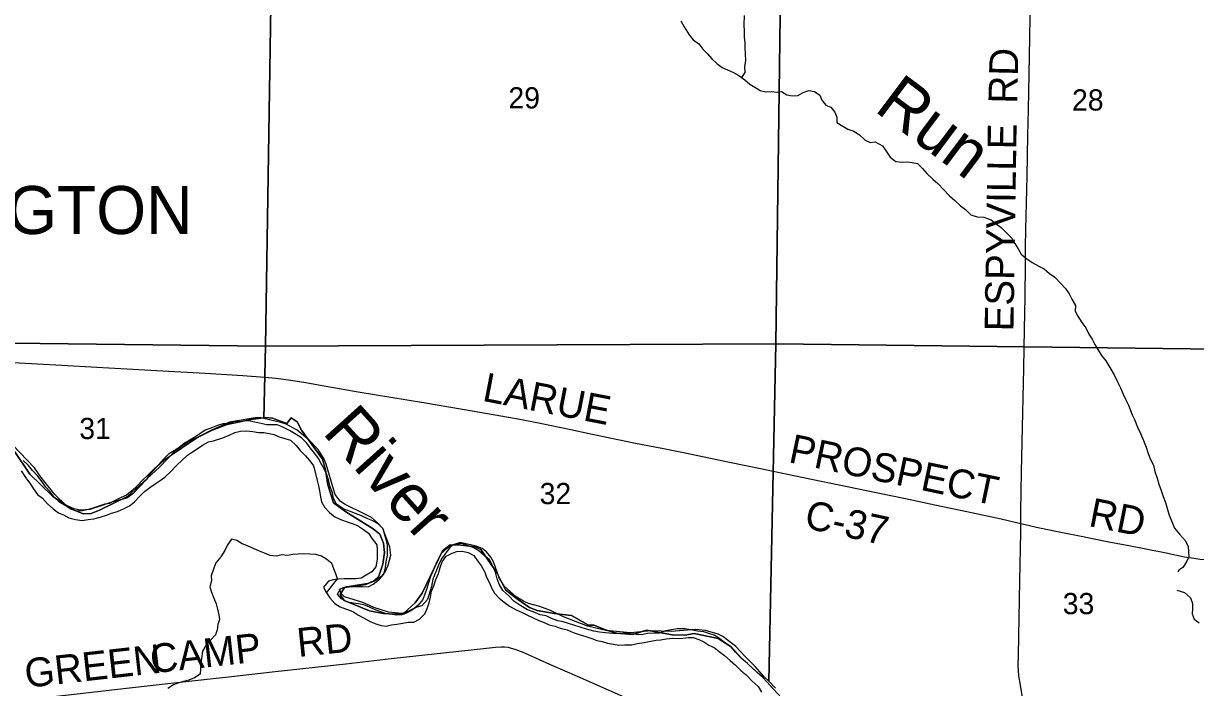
# Model space of a CAD drawing. Extents: x 1584893 to 1934202, y 663575 to 1091909.
# Drawn here: x 1748072 to 1760284, y 934048 to 940964 of the extents above; entities that cross this region are included whole.
import ezdxf

# ---------------------------------------------------------------- set-up
doc = ezdxf.new("R2010")
doc.units = 0
for name, color, linetype in [('GM_X_Corporation_Text', 7, 'Continuous'), ('GM_X_County_Road', 7, 'Continuous'), ('GM_X_County_Road_Text', 7, 'Continuous'), ('GM_X_Major_River', 7, 'Continuous'), ('GM_X_Major_River_Text', 7, 'Continuous'), ('GM_X_Minor_River', 7, 'Continuous'), ('GM_X_Minor_River_Text', 7, 'Continuous'), ('GM_X_Section', 7, 'Continuous'), ('GM_X_Section_Text', 7, 'Continuous'), ('GM_X_Township', 7, 'Continuous'), ('GM_X_Township_Road', 7, 'Continuous'), ('GM_X_Township_Road_Text', 7, 'Continuous')]:
    doc.layers.add(name, color=color, linetype=linetype)

msp = doc.modelspace()

# ---------------------------------------------------------------- linework, layer by layer
at = {"layer": 'GM_X_County_Road'}
for points in [[(1747704, 937447), (1748409, 937408), (1748900, 937380), (1749523, 937347), (1749965, 937321), (1750358, 937297), (1750588, 937281), (1750702, 937270), (1750832, 937253), (1750995, 937228), (1751205, 937192), (1751561, 937129), (1752240, 937015), (1752645, 936949), (1752985, 936890), (1753243, 936844), (1753437, 936806), (1753774, 936736), (1753967, 936695), (1754433, 936598), (1754739, 936537), (1754948, 936495), (1755446, 936392), (1755735, 936333), (1756266, 936223), (1756555, 936163), (1756973, 936076), (1757262, 936017), (1757567, 935952), (1757968, 935866), (1758257, 935804), (1758417, 935767), (1758465, 935757)], [(1758465, 935757), (1758657, 935713), (1758914, 935659), (1759091, 935624), (1759381, 935566), (1759590, 935526), (1759977, 935450), (1760170, 935411), (1760267, 935394), (1760331, 935386), (1760397, 935381), (1760495, 935378), (1760774, 935374), (1760938, 935372), (1761020, 935368), (1761062, 935363)], [(1747714, 933881), (1747761, 933886), (1748511, 933970), (1749147, 934042), (1749701, 934105), (1750239, 934164), (1750663, 934213), (1751430, 934296), (1751903, 934349), (1752896, 934460), (1752991, 934469), (1753049, 934473), (1753084, 934472), (1753123, 934468), (1753154, 934460), (1753192, 934449), (1753269, 934419), (1753584, 934278), (1753840, 934168), (1754320, 933956), (1754513, 933871)]]:
    msp.add_lwpolyline(points, dxfattribs=at)
at = {"layer": 'GM_X_Major_River'}
for points in [[(1751025, 936594), (1750970, 936649), (1750915, 936684), (1750845, 936725), (1750768, 936762), (1750716, 936785), (1750656, 936784), (1750604, 936785), (1750550, 936798), (1750498, 936807), (1750438, 936822), (1750380, 936825), (1750326, 936814), (1750268, 936819), (1750202, 936796), (1750150, 936793), (1750093, 936777), (1750025, 936749), (1749964, 936727), (1749910, 936692), (1749857, 936657), (1749806, 936624), (1749748, 936591), (1749693, 936547), (1749642, 936512), (1749584, 936477), (1749527, 936424), (1749482, 936370), (1749423, 936315), (1749364, 936256), (1749313, 936209), (1749258, 936148), (1749201, 936098), (1749146, 936051), (1749090, 936026), (1749021, 935991), (1748969, 935966), (1748919, 935959), (1748868, 935939), (1748804, 935920), (1748749, 935901), (1748689, 935890), (1748631, 935885), (1748567, 935906), (1748506, 935943), (1748450, 935974), (1748393, 936032), (1748352, 936086), (1748303, 936139), (1748268, 936190), (1748222, 936249), (1748165, 936308), (1748126, 936361), (1748069, 936412)], [(1748049, 936304), (1748094, 936237), (1748137, 936176), (1748178, 936119), (1748219, 936058), (1748271, 936019), (1748322, 935960), (1748381, 935911), (1748436, 935868), (1748488, 935847), (1748544, 935816), (1748614, 935797), (1748685, 935788), (1748748, 935797), (1748806, 935804), (1748870, 935823), (1748939, 935844), (1748989, 935865), (1749053, 935882), (1749114, 935911), (1749177, 935940), (1749229, 935982), (1749280, 936039), (1749335, 936090), (1749390, 936131), (1749443, 936171), (1749495, 936206), (1749546, 936239), (1749607, 936298), (1749666, 936361), (1749725, 936417), (1749782, 936468), (1749832, 936503), (1749883, 936534), (1749936, 936574), (1750000, 936607), (1750051, 936618), (1750151, 936648), (1750214, 936677), (1750276, 936704), (1750335, 936717), (1750395, 936722), (1750461, 936713), (1750521, 936706), (1750575, 936705), (1750631, 936694), (1750684, 936682), (1750738, 936659), (1750794, 936642), (1750854, 936623), (1750913, 936568), (1750956, 936517), (1751011, 936462), (1751056, 936409), (1751094, 936356), (1751107, 936304), (1751133, 936203), (1751146, 936149), (1751155, 936098), (1751166, 936034), (1751178, 935984), (1751209, 935927), (1751260, 935872), (1751315, 935825), (1751387, 935794), (1751444, 935775), (1751496, 935758), (1751554, 935735), (1751615, 935694), (1751667, 935655), (1751706, 935596), (1751753, 935535), (1751758, 935483), (1751759, 935431), (1751758, 935381), (1751745, 935307), (1751702, 935253), (1751644, 935218), (1751589, 935189), (1751535, 935180), (1751413, 935182), (1751355, 935177), (1751300, 935170), (1751250, 935156), (1751199, 935093), (1751228, 935034)], [(1754697, 934616), (1754647, 934615), (1754573, 934610), (1754513, 934597), (1754459, 934600), (1754395, 934609), (1754333, 934614), (1754275, 934609), (1754213, 934610), (1754135, 934617), (1754075, 934626), (1754015, 934636), (1753939, 934655), (1753871, 934678), (1753808, 934699), (1753752, 934714), (1753694, 934733), (1753640, 934744), (1753573, 934769), (1753519, 934794), (1753457, 934805), (1753381, 934836), (1753324, 934857), (1753254, 934899), (1753181, 934948), (1753128, 935003), (1753067, 935058), (1753030, 935125), (1753009, 935179), (1752990, 935250), (1752963, 935311), (1752926, 935379), (1752872, 935424), (1752817, 935473), (1752764, 935502), (1752700, 935527), (1752640, 935550), (1752590, 935543), (1752534, 935528), (1752483, 935495), (1752424, 935444), (1752393, 935386), (1752368, 935332), (1752345, 935275), (1752312, 935205), (1752293, 935139), (1752276, 935081), (1752253, 935020), (1752234, 934964), (1752183, 934906), (1752124, 934859), (1752064, 934822), (1752013, 934807), (1751955, 934802), (1751899, 934811), (1751843, 934818), (1751784, 934839), (1751728, 934860), (1751676, 934887), (1751619, 934910), (1751563, 934921), (1751509, 934926), (1751451, 934938), (1751385, 934972), (1751344, 935022), (1751375, 935076), (1751440, 935101), (1751492, 935098), (1751552, 935101), (1751606, 935100), (1751664, 935097), (1751714, 935125), (1751783, 935176), (1751826, 935229), (1751845, 935297), (1751852, 935357), (1751865, 935423), (1751866, 935481), (1751865, 935537), (1751848, 935600), (1751835, 935650), (1751820, 935700), (1751767, 935753), (1751711, 935786), (1751659, 935805), (1751594, 935836), (1751538, 935857), (1751478, 935880), (1751403, 935908), (1751335, 935959), (1751302, 936018), (1751291, 936076), (1751268, 936139), (1751253, 936197), (1751236, 936255), (1751213, 936312), (1751180, 936367), (1751147, 936433), (1751108, 936484), (1751061, 936543), (1751025, 936594)], [(1751228, 935034), (1751263, 934982), (1751318, 934925), (1751372, 934888), (1751438, 934863), (1751503, 934839), (1751555, 934804), (1751608, 934777), (1751692, 934734), (1751744, 934711), (1751799, 934694), (1751851, 934687), (1751906, 934700), (1751962, 934708), (1752024, 934719), (1752080, 934730), (1752140, 934729), (1752199, 934760), (1752254, 934817), (1752279, 934871), (1752298, 934929), (1752313, 934988), (1752324, 935052), (1752347, 935106), (1752370, 935172), (1752395, 935236), (1752412, 935300), (1752435, 935357), (1752476, 935415), (1752538, 935446), (1752589, 935465), (1752643, 935468), (1752707, 935453), (1752766, 935422), (1752803, 935367), (1752845, 935311), (1752880, 935250), (1752895, 935197), (1752926, 935137), (1752953, 935080), (1752980, 935030), (1753029, 934979), (1753081, 934936), (1753136, 934895), (1753206, 934859), (1753269, 934830), (1753325, 934803), (1753376, 934776), (1753442, 934747), (1753496, 934726), (1753548, 934703), (1753611, 934686), (1753663, 934665), (1753737, 934648), (1753798, 934623), (1753862, 934600), (1753932, 934579), (1753994, 934560), (1754047, 934539), (1754103, 934528), (1754157, 934511), (1754221, 934500), (1754275, 934491), (1754339, 934492), (1754409, 934493), (1754467, 934506), (1754540, 934517), (1754608, 934531), (1754664, 934541), (1754714, 934544), (1754769, 934555), (1754837, 934562), (1754893, 934559), (1754943, 934564), (1754999, 934571), (1755051, 934568), (1755107, 934549), (1755160, 934524), (1755214, 934491), (1755268, 934464), (1755321, 934425), (1755376, 934382), (1755434, 934331), (1755489, 934282), (1755550, 934223), (1755601, 934182), (1755664, 934115), (1755726, 934058), (1755761, 934001)], [(1755872, 934045), (1755822, 934104), (1755769, 934161), (1755718, 934206), (1755667, 934249), (1755615, 934298), (1755554, 934351), (1755491, 934417), (1755444, 934472), (1755375, 934517), (1755323, 934558), (1755268, 934595), (1755214, 934610), (1755162, 934629), (1755094, 934636), (1755024, 934651), (1754964, 934660), (1754888, 934659), (1754824, 934650), (1754762, 934639), (1754697, 934616)]]:
    msp.add_lwpolyline(points, dxfattribs=at)
at = {"layer": 'GM_X_Minor_River'}
for points in [[(1755556, 940401), (1755592, 940452), (1755589, 940512), (1755598, 940580), (1755595, 940649), (1755592, 940709), (1755593, 940765), (1755584, 940819), (1755583, 940885), (1755582, 940949), (1755586, 941046)], [(1754920, 940990), (1754955, 940930), (1755008, 940845), (1755051, 940792), (1755108, 940751), (1755149, 940696), (1755200, 940647), (1755244, 940596), (1755295, 940547), (1755352, 940504), (1755406, 940481), (1755470, 940454), (1755527, 940423), (1755589, 940376), (1755640, 940331), (1755691, 940300), (1755749, 940265), (1755807, 940252), (1755865, 940255), (1755919, 940250), (1755971, 940255), (1756024, 940222), (1756084, 940209), (1756140, 940215), (1756197, 940244), (1756255, 940267), (1756315, 940256), (1756369, 940217)], [(1756369, 940217), (1756390, 940164), (1756433, 940113), (1756485, 940091), (1756526, 940040), (1756547, 939987), (1756546, 939933), (1756608, 939894), (1756661, 939863), (1756723, 939842), (1756784, 939803), (1756842, 939750), (1756893, 939725), (1756947, 939730), (1757021, 939689), (1757060, 939634), (1757103, 939573), (1757160, 939526), (1757230, 939519), (1757280, 939522), (1757332, 939515), (1757386, 939504), (1757438, 939455), (1757483, 939400), (1757546, 939341), (1757597, 939298), (1757662, 939233), (1757721, 939168), (1757776, 939121), (1757836, 939066), (1757887, 939027), (1757942, 938972), (1758008, 938951), (1758078, 938946), (1758154, 938920), (1758205, 938879), (1758258, 938840), (1758314, 938783), (1758369, 938728), (1758402, 938671), (1758437, 938617), (1758466, 938562), (1758517, 938519), (1758581, 938476), (1758650, 938437), (1758706, 938408), (1758761, 938361), (1758817, 938322), (1758876, 938261), (1758927, 938204), (1758966, 938147), (1758993, 938092), (1759032, 938026), (1759029, 937967), (1759056, 937915), (1759099, 937850), (1759140, 937795), (1759173, 937730), (1759205, 937676), (1759234, 937621), (1759267, 937570), (1759304, 937506), (1759349, 937449), (1759390, 937382), (1759437, 937305), (1759462, 937246), (1759503, 937168), (1759530, 937105), (1759555, 937052), (1759584, 936990), (1759622, 936889), (1759647, 936838), (1759678, 936760), (1759711, 936695), (1759742, 936620), (1759769, 936550), (1759786, 936495), (1759811, 936429), (1759844, 936364), (1759859, 936299), (1759882, 936227), (1759901, 936166), (1759926, 936102), (1759945, 936037), (1759972, 935975), (1759991, 935902), (1760008, 935844), (1760035, 935779), (1760065, 935709), (1760116, 935644)], [(1751228, 935034), (1751343, 935179), (1751328, 935233), (1751306, 935284), (1751285, 935340), (1751234, 935383), (1751178, 935416), (1751117, 935433), (1751055, 935436), (1750995, 935441), (1750936, 935438), (1750878, 935433), (1750826, 935424), (1750764, 935431), (1750710, 935418), (1750642, 935425), (1750584, 935448), (1750530, 935469), (1750477, 935492), (1750407, 935523), (1750351, 935544), (1750294, 935579), (1750238, 935592), (1750197, 935533), (1750170, 935475), (1750127, 935409), (1750076, 935346), (1750055, 935292), (1750028, 935211), (1750031, 935158), (1750014, 935097), (1750033, 935042), (1750054, 934978), (1750079, 934919), (1750094, 934865), (1750107, 934806), (1750116, 934756), (1750097, 934704), (1750089, 934650), (1750072, 934596), (1750017, 934537), (1749974, 934486), (1749937, 934426), (1749928, 934352), (1749919, 934300), (1749916, 934242), (1749913, 934188), (1749854, 934151), (1749796, 934124), (1749741, 934110), (1749691, 934097), (1749635, 934076), (1749578, 934039)], [(1760116, 935644), (1760178, 935575), (1760207, 935516), (1760213, 935408), (1760189, 935356), (1760150, 935299), (1760110, 935272), (1760100, 935253)], [(1760087, 935064), (1760170, 935038), (1760230, 934981), (1760253, 934923), (1760253, 934871), (1760250, 934817), (1760269, 934762), (1760322, 934721)]]:
    msp.add_lwpolyline(points, dxfattribs=at)
at = {"layer": 'GM_X_Section'}
for points in [[(1744794, 942974), (1750676, 942925), (1750595, 937603), (1744717, 937672), (1744791, 942835)], [(1750676, 942925), (1755981, 942886), (1755912, 937626), (1750595, 937603)], [(1755981, 942886), (1761209, 942861), (1761100, 937622), (1761097, 937566), (1755912, 937626)], [(1750595, 937603), (1755912, 937626), (1755838, 934116), (1755791, 934156), (1755694, 934267), (1755590, 934372), (1755493, 934475), (1755358, 934580), (1755309, 934605), (1755177, 934642), (1755075, 934653), (1754823, 934633), (1754609, 934639), (1754435, 934623), (1754397, 934619), (1754141, 934641), (1753947, 934689), (1753700, 934785), (1753564, 934850), (1753453, 934893), (1753333, 934922), (1753281, 934947), (1753204, 934994), (1753085, 935099), (1753027, 935191), (1752971, 935356), (1752943, 935406), (1752896, 935462), (1752852, 935495), (1752788, 935521), (1752621, 935559), (1752550, 935534), (1752516, 935506), (1752429, 935387), (1752397, 935323), (1752339, 935177), (1752323, 935100), (1752281, 934966), (1752223, 934898), (1752169, 934885), (1752052, 934830), (1752016, 934820), (1751876, 934833), (1751721, 934881), (1751609, 934934), (1751417, 934992), (1751384, 935028), (1751366, 935074), (1751395, 935088), (1751442, 935101), (1751681, 935139), (1751721, 935155), (1751814, 935216), (1751840, 935252), (1751872, 935322), (1751899, 935427), (1751890, 935511), (1751816, 935704), (1751760, 935765), (1751699, 935819), (1751621, 935856), (1751418, 935958), (1751372, 935990), (1751321, 936059), (1751305, 936103), (1751226, 936376), (1751204, 936426), (1751141, 936526), (1751050, 936623), (1750923, 936728), (1750810, 936791), (1750754, 936810), (1750578, 936849)]]:
    msp.add_lwpolyline(points, close=True, dxfattribs=at)
for points in [[(1744717, 937672), (1750595, 937603), (1750578, 936849), (1750544, 936856), (1750488, 936856), (1750220, 936811), (1750031, 936730), (1749910, 936665), (1749538, 936417), (1749459, 936345), (1749383, 936260), (1749352, 936212), (1749213, 936065), (1749150, 936022), (1748978, 935976), (1748902, 935946), (1748763, 935901), (1748663, 935894), (1748599, 935911), (1748512, 935946), (1748399, 936059), (1748256, 936236), (1748187, 936337), (1747884, 936653)], [(1755908, 934043), (1755838, 934116), (1755912, 937626), (1761097, 937566)]]:
    msp.add_lwpolyline(points, dxfattribs=at)
at = {"layer": 'GM_X_Township'}
for points in [[(1756080, 933821), (1755775, 934154), (1755551, 934358), (1755444, 934471), (1755310, 934558), (1755060, 934612), (1754963, 934595), (1754835, 934597), (1754562, 934646), (1754421, 934601), (1754251, 934613), (1754146, 934645), (1754016, 934698), (1753959, 934698), (1753782, 934800), (1753602, 934820), (1753425, 934852), (1753345, 934883), (1753219, 934967), (1753094, 935065), (1753008, 935240), (1752839, 935487), (1752780, 935514), (1752628, 935532), (1752518, 935534), (1752438, 935472), (1752227, 935031), (1752154, 934931), (1752033, 934819), (1751943, 934812), (1751821, 934819), (1751677, 934847), (1751412, 934954), (1751371, 935018), (1751418, 935089), (1751638, 935121), (1751721, 935158), (1751773, 935207), (1751815, 935332), (1751834, 935454), (1751824, 935553), (1751786, 935646), (1751715, 935701), (1751430, 935878), (1751303, 935972), (1751242, 936159), (1751219, 936317), (1751188, 936428), (1750969, 936729), (1750924, 936816), (1750863, 936856), (1750817, 936798), (1750667, 936854), (1750594, 936862), (1750440, 936840), (1750196, 936788), (1750038, 936727), (1749779, 936599), (1749655, 936517), (1749488, 936345), (1749157, 936037), (1748865, 935895), (1748776, 935861), (1748693, 935858), (1748575, 935905), (1748376, 936041), (1748137, 936270), (1747981, 936503)], [(1747981, 936503), (1748137, 936270), (1748376, 936041), (1748575, 935905), (1748693, 935858), (1748776, 935861), (1748865, 935895), (1749157, 936037), (1749488, 936345), (1749655, 936517), (1749779, 936599), (1750038, 936727), (1750196, 936788), (1750440, 936840), (1750594, 936862), (1750667, 936854), (1750817, 936798), (1750863, 936856), (1750924, 936816), (1750969, 936729), (1751188, 936428), (1751219, 936317), (1751242, 936159), (1751303, 935972), (1751430, 935878), (1751715, 935701), (1751786, 935646), (1751824, 935553), (1751834, 935454), (1751815, 935332), (1751773, 935207), (1751721, 935158), (1751638, 935121), (1751418, 935089), (1751371, 935018), (1751412, 934954), (1751677, 934847), (1751821, 934819), (1751943, 934812), (1752033, 934819), (1752154, 934931), (1752227, 935031), (1752438, 935472), (1752518, 935534), (1752628, 935532), (1752780, 935514), (1752839, 935487), (1753008, 935240), (1753094, 935065), (1753219, 934967), (1753345, 934883), (1753425, 934852), (1753602, 934820), (1753782, 934800), (1753959, 934698), (1754016, 934698), (1754146, 934645), (1754251, 934613), (1754421, 934601), (1754562, 934646), (1754835, 934597), (1754963, 934595), (1755060, 934612), (1755310, 934558), (1755444, 934471), (1755551, 934358), (1755775, 934154), (1756080, 933821)]]:
    msp.add_lwpolyline(points, dxfattribs=at)
at = {"layer": 'GM_X_Township_Road'}
for points in [[(1758465, 935757), (1758464, 935881), (1758468, 936095), (1758472, 936291), (1758478, 936603), (1758494, 937374), (1758500, 937784), (1758507, 938112), (1758511, 938456), (1758513, 938637), (1758517, 938817), (1758528, 939375), (1758536, 939801), (1758543, 940064), (1758557, 940818), (1758560, 941032), (1758565, 941425), (1758570, 941704), (1758578, 942393), (1758582, 942623), (1758587, 942836), (1758588, 942872)], [(1758509, 933510), (1758515, 933544), (1758520, 933592), (1758523, 933641), (1758522, 933690), (1758518, 933738), (1758509, 933803), (1758482, 933948), (1758453, 934110), (1758443, 934175), (1758439, 934224), (1758437, 934274), (1758439, 934389), (1758453, 935160), (1758463, 935668), (1758465, 935734), (1758465, 935757)]]:
    msp.add_lwpolyline(points, dxfattribs=at)

# ---------------------------------------------------------------- texts
at = {"layer": 'GM_X_Corporation_Text'}
msp.add_text('BLOOMINGTON', height=500, rotation=0, dxfattribs=at).set_placement((1744818, 938771))
at = {"layer": 'GM_X_County_Road_Text'}
for s, rotation, p in [('LARUE', 349.0135, (1752843, 937036)), ('PROSPECT', 348.147, (1756033, 936397)), ('RD', 348.6915, (1759159, 935732)), ('C-37', 347.6195, (1756196, 935713)), ('RD', 5.9559, (1750937, 934366)), ('CAMP', 6.3137, (1749409, 934195)), ('GREEN', 6.4084, (1748102, 934045))]:
    msp.add_text(s, height=300, rotation=rotation, dxfattribs=at).set_placement(p)
at = {"layer": 'GM_X_Major_River_Text'}
msp.add_text('River', height=500.2, rotation=312.0142, dxfattribs=at).set_placement((1751176, 936701))
at = {"layer": 'GM_X_Minor_River_Text'}
msp.add_text('Run', height=500.1, rotation=323.1733, dxfattribs=at).set_placement((1756925, 940059))
at = {"layer": 'GM_X_Section_Text'}
for s, p in [('29', (1753125, 940079)), ('28', (1758997, 940057)), ('31', (1748654, 936636)), ('32', (1753450, 935958)), ('33', (1758900, 934812))]:
    msp.add_text(s, height=221, rotation=0, dxfattribs=at).set_placement(p)
at = {"layer": 'GM_X_Township_Road_Text'}
for s, rotation, p in [('RD', 88.6351, (1758425, 940126)), ('ESPYVILLE', 89.1008, (1758386, 937756))]:
    msp.add_text(s, height=300, rotation=rotation, dxfattribs=at).set_placement(p)

doc.saveas('drawing.dxf')
